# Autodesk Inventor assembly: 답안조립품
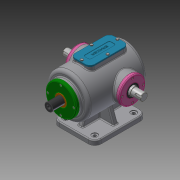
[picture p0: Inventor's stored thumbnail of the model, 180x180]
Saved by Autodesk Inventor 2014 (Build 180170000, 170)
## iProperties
Created: 2021-11
Part Number: 답안조립품
Document SubType Name: Assembly
Designer: kb542-12
Author: kb542-12
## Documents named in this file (14)
- C:\Users\kb542-12\Desktop\711106V1003\답안조립품.iam
- C:\Users\kb542-12\Desktop\711106V1003\답안본체.ipt
- C:\Users\kb542-12\Desktop\711106V1003\베어링 6205.ipt
- 베어링 6205.ipt
- C:\Users\kb542-12\Desktop\711106V1003\볼트 M4x0.7.ipt
- C:\Users\kb542-12\Desktop\711106V1003\부시.ipt
- C:\Users\kb542-12\Desktop\711106V1003\상부커버.ipt
- C:\Users\kb542-12\Desktop\711106V1003\슬라이드 커버.ipt
- C:\Users\kb542-12\Desktop\711106V1003\슬라이드.ipt
- C:\Users\kb542-12\Desktop\711106V1003\오일실.ipt
- 오일실.ipt
- C:\Users\kb542-12\Desktop\711106V1003\육각머리볼트 M4.ipt
- C:\Users\kb542-12\Desktop\711106V1003\축 커버.ipt
- C:\Users\kb542-12\Desktop\711106V1003\편심축.ipt
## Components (12 placed, 1 different names)
1. M4x0.7:1
2. M4x0.7:4
3. M4x0.7:5
4. M4x0.7:6
5. M4x0.7:2
6. M4x0.7:7
7. M4x0.7:8
8. M4x0.7:9
9. M4x0.7:3
10. M4x0.7:10
11. M4x0.7:11
12. M4x0.7:12
